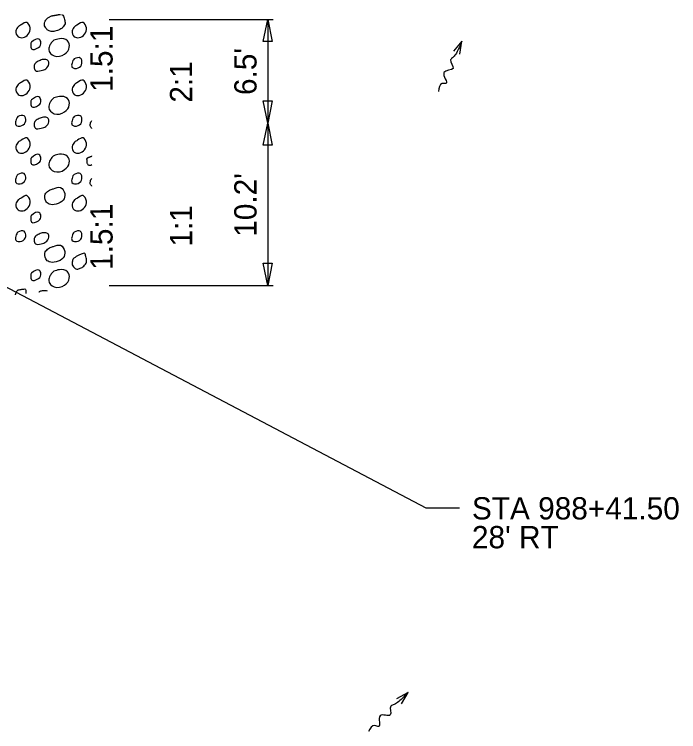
# Model space of a CAD drawing. Extents: x 0 to 486, y 0 to 220.
# Drawn here: x 150.63 to 192.37, y 111.46 to 156.56 of the extents above; entities that cross this region are included whole.
import ezdxf

# ---------------------------------------------------------------- set-up
doc = ezdxf.new("R2010")
doc.units = 0
for name, color, linetype in [('DT_P_Slope_Break_Line', 7, 'Continuous'), ('GE_X_Alignment', 7, 'Continuous'), ('GE_X_Alignment_100_Cardinal_Points', 7, 'Continuous'), ('SC_Scratch1', 7, 'Continuous'), ('SV_X_Shot_Marker', 7, 'Continuous')]:
    doc.layers.add(name, color=color, linetype=linetype)

msp = doc.modelspace()

# ---------------------------------------------------------------- linework, layer by layer
at = {"layer": 'DT_P_Slope_Break_Line'}
for p, q in [((178.752, 154.879), (178.22, 154.244)), ((178.609, 154.064), (178.752, 154.879)), ((175.365, 113.934), (174.646, 113.521)), ((174.95, 113.217), (175.365, 113.934))]:
    msp.add_line(p, q, dxfattribs=at)
for points in [[(178.752, 154.879), (178.4, 154.127), (178.193, 153.86), (178.039, 153.702), (178.194, 153.162), (177.615, 152.896), (177.753, 152.215), (177.503, 152.206), (177.277, 151.705)], [(175.365, 113.934), (174.775, 113.349), (174.489, 113.17), (174.29, 113.074), (174.249, 112.514), (173.614, 112.464), (173.509, 111.776), (173.271, 111.854), (172.887, 111.462)]]:
    msp.add_spline(points, degree=3, dxfattribs=at)
at = {"layer": 'GE_X_Alignment'}
for points in [[(166.825, 154.845), (166.265, 154.845), (166.545, 156.245)], [(166.265, 151.127), (166.825, 151.127), (166.545, 149.727)], [(166.825, 148.327), (166.265, 148.327), (166.545, 149.727)], [(166.265, 140.913), (166.825, 140.913), (166.545, 139.513)]]:
    msp.add_lwpolyline(points, close=True, dxfattribs=at)
at = {"layer": 'GE_X_Alignment_100_Cardinal_Points'}
for p, q in [((156.587, 156.245), (166.897, 156.245)), ((166.545, 156.245), (166.545, 149.727)), ((176.497, 125.503), (130.5, 149.727)), ((166.545, 149.727), (166.545, 139.513)), ((156.587, 139.513), (166.897, 139.513))]:
    msp.add_line(p, q, dxfattribs=at)
at = {"layer": 'SC_Scratch1'}
msp.add_line((178.604, 125.503), (176.497, 125.503), dxfattribs=at)
msp.add_line((178.604, 125.503), (176.497, 125.503), dxfattribs=at)
at = {"layer": 'SV_X_Shot_Marker'}
for points, degree in [([(153.599, 156.548), (153.704, 156.497), (153.758, 156.297), (153.789, 156.179), (153.824, 156.05), (153.801, 155.892), (153.693, 155.772), (153.559, 155.624), (153.411, 155.568), (153.247, 155.519), (153.105, 155.478), (152.947, 155.463), (152.807, 155.522), (152.721, 155.558), (152.659, 155.62), (152.608, 155.7), (152.521, 155.834), (152.495, 156.019), (152.571, 156.145), (152.621, 156.229), (152.689, 156.303), (152.776, 156.359), (152.85, 156.406), (152.92, 156.45), (153.002, 156.467), (153.029, 156.473), (153.057, 156.479), (153.084, 156.484)], 3), ([(153.076, 156.483), (153.227, 156.509), (153.379, 156.537), (153.53, 156.559)], 2), ([(155.5, 149.386), (155.495, 149.39), (155.49, 149.394), (155.485, 149.398), (155.412, 149.464), (155.397, 149.54), (155.399, 149.614), (155.401, 149.681), (155.409, 149.759), (155.451, 149.814), (155.467, 149.836), (155.484, 149.857), (155.5, 149.879)], 3), ([(155.5, 147.088), (155.388, 147.043), (155.27, 147.042), (155.235, 147.132), (155.204, 147.21), (155.199, 147.291), (155.196, 147.372), (155.194, 147.412), (155.179, 147.457), (155.2, 147.493), (155.211, 147.511), (155.222, 147.527), (155.233, 147.544)], 3), ([(155.233, 147.544), (155.322, 147.58), (155.411, 147.618), (155.5, 147.654)], 2), ([(155.5, 145.756), (155.495, 145.759), (155.49, 145.764), (155.485, 145.768), (155.412, 145.833), (155.397, 145.909), (155.399, 145.984), (155.401, 146.05), (155.409, 146.128), (155.451, 146.184), (155.467, 146.206), (155.484, 146.227), (155.5, 146.248)], 3), ([(154.592, 141.378), (154.709, 141.429), (154.826, 141.479), (154.943, 141.529), (155.065, 141.581), (155.124, 141.315), (155.151, 141.191), (155.179, 141.06), (155.145, 140.913), (155.039, 140.786), (154.939, 140.666), (154.826, 140.61), (154.706, 140.573), (154.61, 140.544), (154.489, 140.54), (154.395, 140.633), (154.281, 140.745), (154.239, 140.877), (154.262, 140.992), (154.28, 141.083), (154.322, 141.203), (154.408, 141.259), (154.469, 141.3), (154.53, 141.338), (154.592, 141.378)], 3), ([(150.702, 138.928), (150.705, 138.943), (150.709, 138.958), (150.713, 138.972), (150.729, 139.027), (150.736, 139.09), (150.772, 139.135), (150.798, 139.169), (150.825, 139.203), (150.852, 139.236)], 3), ([(150.852, 139.236), (150.979, 139.255), (151.106, 139.275), (151.233, 139.292), (151.333, 139.305), (151.365, 139.119), (151.348, 139.007)], 3), ([(152.162, 139.106), (152.188, 139.119), (152.213, 139.132), (152.239, 139.145), (152.331, 139.19), (152.44, 139.199), (152.54, 139.202), (152.59, 139.203), (152.639, 139.196), (152.686, 139.17)], 3)]:
    msp.add_open_spline(points, degree=degree, dxfattribs=at)
for points in [[(151.056, 155.9), (151.408, 156.051), (151.615, 155.713), (151.503, 155.308), (151.17, 155.095), (150.859, 155.154), (150.726, 155.514), (150.872, 155.781), (151.056, 155.9)], [(154.592, 155.9), (154.943, 156.051), (155.151, 155.713), (155.039, 155.308), (154.706, 155.095), (154.395, 155.154), (154.262, 155.514), (154.408, 155.781), (154.592, 155.9)], [(151.698, 154.805), (152.173, 154.998), (152.298, 154.779), (152.149, 154.477), (151.699, 154.393), (151.66, 154.633), (151.664, 154.754), (151.698, 154.805)], [(153.097, 154.931), (153.453, 155.024), (153.973, 154.893), (154.081, 154.49), (153.785, 154.055), (153.137, 153.944), (152.783, 154.343), (152.878, 154.661), (153.016, 154.854), (153.097, 154.931)], [(154.388, 153.758), (154.769, 153.814), (154.873, 153.486), (154.633, 153.191), (154.247, 153.248), (154.249, 153.494), (154.308, 153.657), (154.388, 153.758)], [(151.989, 153.541), (152.239, 153.666), (152.54, 153.724), (152.751, 153.643), (152.785, 153.44), (152.614, 153.143), (152.301, 153.023), (151.949, 153.029), (151.863, 153.245), (151.915, 153.445), (151.989, 153.541)], [(151.056, 152.27), (151.408, 152.421), (151.615, 152.082), (151.503, 151.677), (151.17, 151.465), (150.859, 151.524), (150.726, 151.883), (150.872, 152.151), (151.056, 152.27)], [(154.592, 152.27), (154.943, 152.421), (155.151, 152.082), (155.039, 151.677), (154.706, 151.465), (154.395, 151.524), (154.262, 151.883), (154.408, 152.151), (154.592, 152.27)], [(151.698, 151.175), (152.173, 151.367), (152.298, 151.149), (152.149, 150.846), (151.699, 150.762), (151.66, 151.002), (151.664, 151.123), (151.698, 151.175)], [(153.097, 151.301), (153.453, 151.394), (153.973, 151.262), (154.081, 150.86), (153.785, 150.425), (153.137, 150.314), (152.783, 150.712), (152.878, 151.031), (153.016, 151.223), (153.097, 151.301)], [(150.852, 150.128), (151.233, 150.183), (151.338, 149.855), (151.098, 149.561), (150.711, 149.618), (150.713, 149.863), (150.772, 150.027), (150.852, 150.128)], [(154.388, 150.128), (154.769, 150.183), (154.873, 149.855), (154.633, 149.561), (154.247, 149.618), (154.249, 149.863), (154.308, 150.027), (154.388, 150.128)], [(151.989, 149.911), (152.239, 150.036), (152.54, 150.093), (152.751, 150.013), (152.785, 149.809), (152.614, 149.513), (152.301, 149.393), (151.949, 149.398), (151.863, 149.614), (151.915, 149.814), (151.989, 149.911)], [(151.056, 148.639), (151.408, 148.79), (151.615, 148.452), (151.503, 148.047), (151.17, 147.834), (150.859, 147.893), (150.726, 148.253), (150.872, 148.52), (151.056, 148.639)], [(154.592, 148.639), (154.943, 148.79), (155.151, 148.452), (155.039, 148.047), (154.706, 147.834), (154.395, 147.893), (154.262, 148.253), (154.408, 148.52), (154.592, 148.639)], [(151.698, 147.544), (152.173, 147.737), (152.298, 147.518), (152.149, 147.216), (151.699, 147.132), (151.66, 147.372), (151.664, 147.493), (151.698, 147.544)], [(153.097, 147.67), (153.453, 147.763), (153.973, 147.632), (154.081, 147.229), (153.785, 146.794), (153.137, 146.683), (152.783, 147.082), (152.878, 147.4), (153.016, 147.593), (153.097, 147.67)], [(150.852, 146.497), (151.233, 146.553), (151.338, 146.225), (151.098, 145.931), (150.711, 145.987), (150.713, 146.233), (150.772, 146.396), (150.852, 146.497)], [(154.388, 146.497), (154.769, 146.553), (154.873, 146.225), (154.633, 145.931), (154.247, 145.987), (154.249, 146.233), (154.308, 146.396), (154.388, 146.497)], [(153.076, 145.591), (153.53, 145.667), (153.789, 145.287), (153.693, 144.881), (153.247, 144.628), (152.807, 144.631), (152.608, 144.809), (152.571, 145.254), (152.776, 145.467), (153.002, 145.576), (153.084, 145.593)], [(151.056, 145.009), (151.408, 145.16), (151.615, 144.821), (151.503, 144.416), (151.17, 144.204), (150.859, 144.263), (150.726, 144.622), (150.872, 144.89), (151.056, 145.009)], [(154.592, 145.009), (154.943, 145.16), (155.151, 144.821), (155.039, 144.416), (154.706, 144.204), (154.395, 144.263), (154.262, 144.622), (154.408, 144.89), (154.592, 145.009)], [(151.698, 143.914), (152.173, 144.106), (152.298, 143.888), (152.149, 143.586), (151.699, 143.501), (151.66, 143.741), (151.664, 143.862), (151.698, 143.914)], [(150.852, 142.867), (151.233, 142.923), (151.338, 142.594), (151.098, 142.3), (150.711, 142.357), (150.713, 142.603), (150.772, 142.766), (150.852, 142.867)], [(154.388, 142.867), (154.769, 142.923), (154.873, 142.594), (154.633, 142.3), (154.247, 142.357), (154.249, 142.603), (154.308, 142.766), (154.388, 142.867)], [(151.989, 142.65), (152.239, 142.775), (152.54, 142.833), (152.751, 142.752), (152.785, 142.548), (152.614, 142.252), (152.301, 142.132), (151.949, 142.138), (151.863, 142.353), (151.915, 142.553), (151.989, 142.65)], [(153.076, 141.961), (153.53, 142.037), (153.789, 141.657), (153.693, 141.25), (153.247, 140.998), (152.807, 141), (152.608, 141.178), (152.571, 141.623), (152.776, 141.837), (153.002, 141.945), (153.084, 141.963)], [(151.698, 140.283), (152.173, 140.476), (152.298, 140.258), (152.149, 139.955), (151.699, 139.871), (151.66, 140.111), (151.664, 140.232), (151.698, 140.283)], [(153.097, 140.409), (153.453, 140.503), (153.973, 140.371), (154.081, 139.968), (153.785, 139.533), (153.137, 139.423), (152.783, 139.821), (152.878, 140.139), (153.016, 140.332), (153.097, 140.409)]]:
    msp.add_spline(points, degree=3, dxfattribs=at)

# ---------------------------------------------------------------- texts
at = {"layer": 'GE_X_Alignment_100_Cardinal_Points'}
for s, rotation, p in [('1.5:1', 90.0983, (156.803, 151.685)), ("6.5'", 90, (165.845, 151.487)), ('2:1', 90.0983, (161.802, 151.008)), ("10.2'", 90, (165.845, 142.577)), ('1.5:1', 90.0983, (156.803, 140.49)), ('1:1', 90.0983, (161.802, 141.962))]:
    msp.add_text(s, height=1.4, rotation=rotation, dxfattribs=at).set_placement(p)
for s, p in [('STA 988+41.50', (179.377, 124.803)), ("28' RT", (179.377, 122.991))]:
    msp.add_text(s, height=1.4, dxfattribs=at).set_placement(p)

doc.saveas('drawing.dxf')
